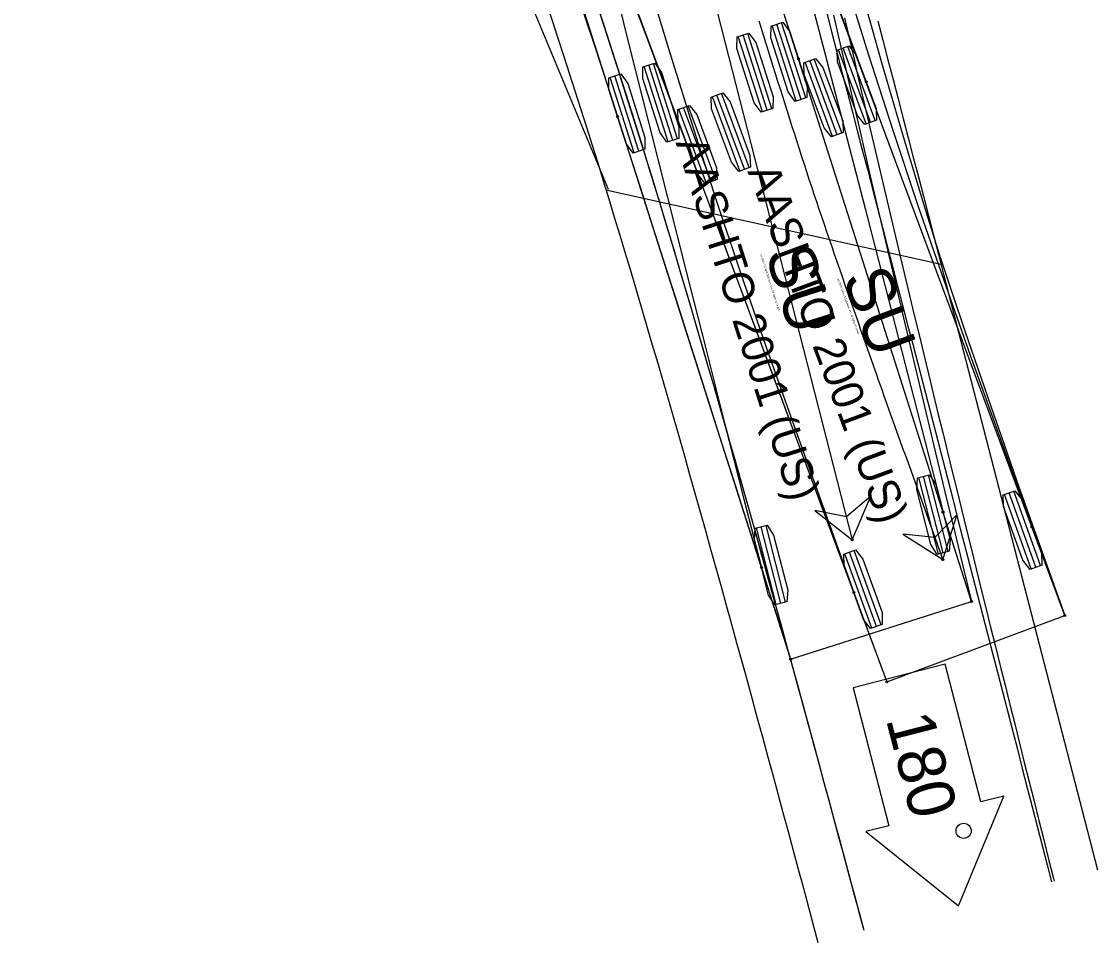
# Model space of a CAD drawing. Extents: x 916040 to 917457, y 328936 to 330267.
# Drawn here: x 916711.68 to 916757.01, y 329739.76 to 329778.57 of the extents above; entities that cross this region are included whole.
import ezdxf

# ---------------------------------------------------------------- set-up
doc = ezdxf.new("R2010")
doc.units = 0
for name, color, linetype in [('D_Roadway_Drive_Gravel', 7, 'Continuous'), ('SU_IntoDriveway', 7, 'Continuous'), ('SU_IntoDriveway_Lt', 7, 'Continuous'), ('SU_IntoDriveway_Rt', 7, 'Continuous')]:
    doc.layers.add(name, color=color, linetype=linetype)

msp = doc.modelspace()

# ---------------------------------------------------------------- linework, layer by layer
at = {"layer": 'D_Roadway_Drive_Gravel'}
msp.add_line((916736.405, 329771.493), (916728.256, 329791.111), dxfattribs=at)
at = {"layer": 'SU_IntoDriveway'}
for p, q in [((916736.303, 329771.473), (916750.419, 329768.338)), ((916750.587, 329751.49), (916746.714, 329750.489)), ((916752.089, 329745.681), (916750.587, 329751.49)), ((916746.714, 329750.489), (916748.216, 329744.68)), ((916751.154, 329741.308), (916753.057, 329745.931)), ((916753.057, 329745.931), (916752.089, 329745.681)), ((916748.216, 329744.68), (916747.248, 329744.43)), ((916747.248, 329744.43), (916751.154, 329741.308))]:
    msp.add_line(p, q, dxfattribs=at)
for points in [[(916733.813, 329779.293), (916734.054, 329778.564), (916734.295, 329777.832), (916734.534, 329777.095), (916734.773, 329776.356), (916735.01, 329775.612), (916735.247, 329774.866), (916735.483, 329774.117), (916735.719, 329773.365), (916735.953, 329772.61), (916736.187, 329771.853), (916736.42, 329771.093), (916736.652, 329770.331), (916736.883, 329769.567), (916737.113, 329768.801), (916737.343, 329768.033), (916737.572, 329767.264), (916737.8, 329766.492), (916738.028, 329765.719), (916738.255, 329764.944), (916738.481, 329764.168), (916738.707, 329763.39), (916738.932, 329762.611), (916739.156, 329761.831), (916739.38, 329761.049), (916739.604, 329760.266), (916739.826, 329759.482), (916740.048, 329758.698), (916740.27, 329757.912), (916740.491, 329757.125), (916740.712, 329756.337), (916740.932, 329755.549), (916741.152, 329754.759), (916741.371, 329753.969), (916741.59, 329753.178), (916741.808, 329752.387), (916742.026, 329751.595), (916742.244, 329750.802), (916742.461, 329750.008), (916742.678, 329749.214), (916742.895, 329748.419), (916743.111, 329747.624), (916743.327, 329746.828), (916743.543, 329746.032), (916743.758, 329745.236), (916743.973, 329744.438), (916744.188, 329743.641), (916744.402, 329742.843), (916744.617, 329742.045), (916744.831, 329741.246), (916745.045, 329740.447), (916745.228, 329739.759)], [(916735.954, 329779.19), (916736.196, 329778.453), (916736.437, 329777.712), (916736.677, 329776.967), (916736.916, 329776.22), (916737.154, 329775.469), (916737.391, 329774.716), (916737.628, 329773.96), (916737.864, 329773.202), (916738.098, 329772.441), (916738.332, 329771.678), (916738.565, 329770.913), (916738.798, 329770.145), (916739.029, 329769.376), (916739.26, 329768.605), (916739.49, 329767.832), (916739.719, 329767.058), (916739.947, 329766.282), (916740.175, 329765.505), (916740.402, 329764.726), (916740.628, 329763.946), (916740.854, 329763.165), (916741.079, 329762.382), (916741.303, 329761.599), (916741.527, 329760.814), (916741.75, 329760.028), (916741.973, 329759.241), (916742.195, 329758.454), (916742.417, 329757.665), (916742.638, 329756.876), (916742.859, 329756.086), (916743.079, 329755.295), (916743.298, 329754.503), (916743.518, 329753.711), (916743.736, 329752.918), (916743.955, 329752.125), (916744.173, 329751.33), (916744.39, 329750.536), (916744.608, 329749.741), (916744.825, 329748.945), (916745.041, 329748.148), (916745.257, 329747.352), (916745.473, 329746.555), (916745.689, 329745.757), (916745.904, 329744.959), (916746.119, 329744.161), (916746.334, 329743.362), (916746.548, 329742.563), (916746.763, 329741.763), (916746.977, 329740.964), (916747.161, 329740.275)], [(916735.954, 329779.19), (916736.196, 329778.453), (916736.437, 329777.712), (916736.677, 329776.967), (916736.916, 329776.22), (916737.154, 329775.469), (916737.391, 329774.716), (916737.628, 329773.96), (916737.864, 329773.202), (916738.098, 329772.441), (916738.332, 329771.678), (916738.565, 329770.913), (916738.798, 329770.145), (916739.029, 329769.376), (916739.26, 329768.605), (916739.49, 329767.832), (916739.719, 329767.058), (916739.947, 329766.282), (916740.175, 329765.505), (916740.402, 329764.726), (916740.628, 329763.946), (916740.854, 329763.165), (916741.079, 329762.382), (916741.303, 329761.599), (916741.527, 329760.814), (916741.75, 329760.028), (916741.973, 329759.241), (916742.195, 329758.454), (916742.417, 329757.665), (916742.638, 329756.876), (916742.859, 329756.086), (916743.079, 329755.295), (916743.298, 329754.503), (916743.518, 329753.711), (916743.736, 329752.918), (916743.955, 329752.125), (916744.173, 329751.33), (916744.39, 329750.536), (916744.608, 329749.741), (916744.825, 329748.945), (916745.041, 329748.148), (916745.257, 329747.352), (916745.473, 329746.555), (916745.689, 329745.757), (916745.904, 329744.959), (916746.119, 329744.161), (916746.334, 329743.362), (916746.548, 329742.563), (916746.763, 329741.763), (916746.977, 329740.964), (916747.161, 329740.275)], [(916735.99, 329779.08), (916736.246, 329778.3), (916736.499, 329777.518), (916736.751, 329776.736), (916737.001, 329775.952), (916737.249, 329775.167), (916737.496, 329774.382), (916737.742, 329773.595), (916737.985, 329772.808), (916738.228, 329772.019), (916738.469, 329771.23), (916738.708, 329770.44), (916738.947, 329769.649), (916739.184, 329768.858), (916739.42, 329768.066), (916739.655, 329767.273), (916739.889, 329766.48), (916740.122, 329765.686), (916740.354, 329764.891), (916740.585, 329764.096), (916740.815, 329763.301), (916741.044, 329762.505), (916741.272, 329761.708), (916741.499, 329760.911), (916741.726, 329760.114), (916741.952, 329759.316), (916742.177, 329758.518), (916742.402, 329757.719), (916742.626, 329756.92), (916742.849, 329756.121), (916743.071, 329755.322), (916743.293, 329754.522), (916743.515, 329753.721), (916743.736, 329752.921), (916743.956, 329752.12), (916744.176, 329751.319), (916744.395, 329750.518), (916744.614, 329749.716), (916744.833, 329748.915), (916745.051, 329748.113), (916745.269, 329747.311), (916745.486, 329746.508), (916745.703, 329745.706), (916745.919, 329744.903), (916746.135, 329744.1), (916746.351, 329743.297), (916746.567, 329742.494), (916746.782, 329741.691), (916746.997, 329740.887), (916747.161, 329740.275)], [(916745.6, 329778.923), (916745.815, 329778.098), (916746.03, 329777.274), (916746.245, 329776.45), (916746.46, 329775.627), (916746.674, 329774.805), (916746.888, 329773.983), (916747.101, 329773.162), (916747.314, 329772.341), (916747.527, 329771.521), (916747.74, 329770.701), (916747.952, 329769.882), (916748.165, 329769.064), (916748.377, 329768.246), (916748.588, 329767.428), (916748.8, 329766.611), (916749.011, 329765.794), (916749.223, 329764.978), (916749.434, 329764.161), (916749.645, 329763.346), (916749.856, 329762.53), (916750.066, 329761.715), (916750.277, 329760.901), (916750.487, 329760.086), (916750.698, 329759.272), (916750.908, 329758.458), (916751.118, 329757.645), (916751.328, 329756.832), (916751.538, 329756.019), (916751.748, 329755.206), (916751.957, 329754.393), (916752.167, 329753.581), (916752.377, 329752.769), (916752.586, 329751.957), (916752.796, 329751.145), (916753.005, 329750.334), (916753.214, 329749.523), (916753.424, 329748.711), (916753.633, 329747.9), (916753.842, 329747.09), (916754.051, 329746.279), (916754.26, 329745.469), (916754.469, 329744.658), (916754.678, 329743.848), (916754.887, 329743.038), (916755.072, 329742.321)], [(916745.6, 329778.923), (916745.815, 329778.098), (916746.03, 329777.274), (916746.245, 329776.45), (916746.46, 329775.627), (916746.674, 329774.805), (916746.888, 329773.983), (916747.101, 329773.162), (916747.314, 329772.341), (916747.527, 329771.521), (916747.74, 329770.701), (916747.952, 329769.882), (916748.165, 329769.064), (916748.377, 329768.246), (916748.588, 329767.428), (916748.8, 329766.611), (916749.011, 329765.794), (916749.223, 329764.978), (916749.434, 329764.161), (916749.645, 329763.346), (916749.856, 329762.53), (916750.066, 329761.715), (916750.277, 329760.901), (916750.487, 329760.086), (916750.698, 329759.272), (916750.908, 329758.458), (916751.118, 329757.645), (916751.328, 329756.832), (916751.538, 329756.019), (916751.748, 329755.206), (916751.957, 329754.393), (916752.167, 329753.581), (916752.377, 329752.769), (916752.586, 329751.957), (916752.796, 329751.145), (916753.005, 329750.334), (916753.214, 329749.523), (916753.424, 329748.711), (916753.633, 329747.9), (916753.842, 329747.09), (916754.051, 329746.279), (916754.26, 329745.469), (916754.469, 329744.658), (916754.678, 329743.848), (916754.887, 329743.038), (916755.072, 329742.321)], [(916746.351, 329778.729), (916746.544, 329777.884), (916746.738, 329777.041), (916746.933, 329776.199), (916747.127, 329775.358), (916747.323, 329774.519), (916747.518, 329773.682), (916747.714, 329772.846), (916747.91, 329772.011), (916748.106, 329771.177), (916748.303, 329770.344), (916748.5, 329769.513), (916748.697, 329768.682), (916748.895, 329767.853), (916749.093, 329767.024), (916749.292, 329766.196), (916749.49, 329765.37), (916749.689, 329764.544), (916749.889, 329763.718), (916750.088, 329762.894), (916750.288, 329762.07), (916750.488, 329761.248), (916750.689, 329760.425), (916750.89, 329759.604), (916751.091, 329758.783), (916751.292, 329757.962), (916751.493, 329757.142), (916751.695, 329756.323), (916751.897, 329755.504), (916752.099, 329754.686), (916752.301, 329753.868), (916752.504, 329753.051), (916752.707, 329752.234), (916752.91, 329751.417), (916753.113, 329750.601), (916753.316, 329749.786), (916753.52, 329748.97), (916753.723, 329748.155), (916753.927, 329747.34), (916754.131, 329746.526), (916754.336, 329745.712), (916754.54, 329744.898), (916754.744, 329744.085), (916754.949, 329743.272), (916755.154, 329742.459), (916755.181, 329742.349)], [(916747.75, 329778.603), (916747.966, 329777.779), (916748.18, 329776.954), (916748.395, 329776.131), (916748.609, 329775.308), (916748.823, 329774.486), (916749.037, 329773.665), (916749.25, 329772.844), (916749.463, 329772.024), (916749.676, 329771.204), (916749.888, 329770.384), (916750.101, 329769.566), (916750.313, 329768.747), (916750.524, 329767.929), (916750.736, 329767.112), (916750.948, 329766.295), (916751.159, 329765.478), (916751.37, 329764.662), (916751.581, 329763.846), (916751.792, 329763.031), (916752.003, 329762.216), (916752.213, 329761.401), (916757.009, 329742.821)]]:
    msp.add_lwpolyline(points, dxfattribs=at)
msp.add_circle((916751.371, 329744.463), 0.32, dxfattribs=at)
at = {"layer": 'SU_IntoDriveway_Lt'}
for p, q in [((916736.164, 329797.863), (916746.678, 329756.728)), ((916751.704, 329754.133), (916742.585, 329782.714)), ((916734.964, 329780.282), (916744.083, 329751.702)), ((916744.717, 329775.347), (916743.704, 329778.522)), ((916743.288, 329774.891), (916742.275, 329778.066)), ((916744.32, 329775.22), (916743.307, 329778.396)), ((916744.519, 329775.283), (916743.505, 329778.459)), ((916742.891, 329774.764), (916741.878, 329777.94)), ((916743.09, 329774.827), (916742.076, 329778.003)), ((916739.12, 329773.561), (916738.107, 329776.737)), ((916739.318, 329773.624), (916738.305, 329776.8)), ((916737.691, 329773.105), (916736.678, 329776.281)), ((916737.889, 329773.168), (916736.876, 329776.344)), ((916738.922, 329773.498), (916737.908, 329776.673)), ((916737.493, 329773.042), (916736.479, 329776.217)), ((916750.713, 329756.231), (916749.886, 329759.461)), ((916750.31, 329756.128), (916749.483, 329759.357)), ((916750.512, 329756.18), (916749.684, 329759.409)), ((916743.467, 329753.996), (916742.643, 329757.226)), ((916743.669, 329754.048), (916742.845, 329757.278)), ((916743.871, 329754.099), (916743.047, 329757.329)), ((916744.083, 329751.702), (916751.704, 329754.133)), ((916751.704, 329754.133), (916751.704, 329754.133))]:
    msp.add_line(p, q, dxfattribs=at)
for points in [[(916734.83, 329780.501), (916735.875, 329777.387), (916736.787, 329774.566)], [(916736.501, 329780.691), (916737.284, 329777.544), (916738.076, 329774.384), (916738.875, 329771.214), (916739.68, 329768.034), (916740.489, 329764.845), (916741.302, 329761.649), (916742.117, 329758.447), (916742.853, 329755.56)], [(916744.645, 329780.618), (916745.509, 329777.298), (916746.366, 329773.988), (916747.217, 329770.69), (916748.064, 329767.4), (916748.907, 329764.117), (916749.747, 329760.841), (916750.502, 329757.898)], [(916743.473, 329779.891), (916744.409, 329776.998)], [(916735.34, 329778.996), (916735.827, 329777.533), (916736.31, 329776.054), (916736.789, 329774.561), (916737.269, 329773.058), (916737.751, 329771.545), (916738.237, 329770.024), (916738.724, 329768.496), (916739.214, 329766.962), (916739.705, 329765.422), (916740.198, 329763.877), (916740.692, 329762.327), (916741.188, 329760.774), (916741.685, 329759.217), (916742.183, 329757.656), (916742.682, 329756.093), (916743.181, 329754.527), (916743.682, 329752.958), (916744.083, 329751.702)], [(916745.892, 329778.832), (916746.276, 329777.129), (916746.661, 329775.432), (916747.048, 329773.742), (916747.435, 329772.058), (916747.824, 329770.379), (916748.215, 329768.705), (916748.606, 329767.036), (916749, 329765.371), (916749.394, 329763.71), (916749.789, 329762.052), (916750.186, 329760.397), (916750.584, 329758.745), (916750.983, 329757.096), (916751.383, 329755.449), (916751.704, 329754.133)]]:
    msp.add_lwpolyline(points, dxfattribs=at)
for points in [[(916744.766, 329775.362), (916744.271, 329775.204), (916743.98, 329775.601), (916743.25, 329777.888), (916743.258, 329778.38), (916743.753, 329778.538), (916744.044, 329778.141), (916744.774, 329775.855)], [(916743.337, 329774.906), (916742.842, 329774.748), (916742.551, 329775.145), (916741.821, 329777.432), (916741.829, 329777.924), (916742.324, 329778.082), (916742.615, 329777.685), (916743.345, 329775.399)], [(916739.368, 329773.64), (916738.872, 329773.482), (916738.581, 329773.879), (916737.852, 329776.165), (916737.859, 329776.657), (916738.354, 329776.816), (916738.646, 329776.419), (916739.375, 329774.132)], [(916737.939, 329773.184), (916737.443, 329773.026), (916737.152, 329773.423), (916736.423, 329775.709), (916736.43, 329776.202), (916736.925, 329776.36), (916737.217, 329775.963), (916737.946, 329773.676)], [(916750.763, 329756.244), (916750.26, 329756.115), (916749.992, 329756.528), (916749.397, 329758.853), (916749.433, 329759.344), (916749.936, 329759.473), (916750.204, 329759.06), (916750.799, 329756.735)], [(916746.678, 329756.728), (916747.464, 329758.567), (916746.43, 329757.697), (916745.105, 329757.964)], [(916743.921, 329754.112), (916743.417, 329753.984), (916743.15, 329754.397), (916742.557, 329756.723), (916742.593, 329757.214), (916743.097, 329757.342), (916743.364, 329756.929), (916743.957, 329754.603)]]:
    msp.add_lwpolyline(points, close=True, dxfattribs=at)
for centre in [(916744.409, 329776.998), (916736.787, 329774.566), (916750.502, 329757.898), (916746.678, 329756.728), (916742.853, 329755.56), (916751.704, 329754.133), (916744.083, 329751.702)]:
    msp.add_circle(centre, 0.0417, dxfattribs=at)
at = {"layer": 'SU_IntoDriveway_Rt'}
for p, q in [((916755.636, 329753.539), (916745.168, 329781.653)), ((916737.671, 329778.862), (916748.138, 329750.748)), ((916747.258, 329774.251), (916746.095, 329777.374)), ((916747.453, 329774.323), (916746.29, 329777.447)), ((916747.648, 329774.396), (916746.485, 329777.52)), ((916745.852, 329773.727), (916744.689, 329776.851)), ((916746.047, 329773.8), (916744.884, 329776.924)), ((916746.242, 329773.873), (916745.079, 329776.996)), ((916741.947, 329772.273), (916740.784, 329775.397)), ((916742.142, 329772.346), (916740.979, 329775.47)), ((916742.338, 329772.419), (916741.175, 329775.543)), ((916740.541, 329771.75), (916739.378, 329774.874)), ((916740.737, 329771.823), (916739.574, 329774.947)), ((916740.932, 329771.895), (916739.769, 329775.019)), ((916754.22, 329755.5), (916753.09, 329758.635)), ((916754.416, 329755.57), (916753.286, 329758.706)), ((916754.612, 329755.641), (916753.481, 329758.776)), ((916747.501, 329753.007), (916746.37, 329756.143)), ((916747.697, 329753.078), (916746.566, 329756.213)), ((916747.893, 329753.148), (916746.762, 329756.284)), ((916748.138, 329750.748), (916755.636, 329753.539)), ((916755.636, 329753.539), (916755.636, 329753.539))]:
    msp.add_line(p, q, dxfattribs=at)
for points in [[(916714.9, 329827.336), (916716.624, 329826.516), (916719.394, 329824.952), (916722.017, 329823.153), (916724.473, 329821.132), (916726.744, 329818.905), (916728.813, 329816.489), (916730.676, 329813.886), (916732.407, 329811.043), (916734.015, 329808.062), (916735.521, 329805.02), (916736.959, 329801.953), (916738.338, 329798.858), (916739.658, 329795.744), (916740.929, 329792.618), (916742.163, 329789.488), (916743.371, 329786.359), (916744.562, 329783.229), (916745.741, 329780.1), (916746.912, 329776.97), (916747.262, 329776.031)], [(916711.681, 329820.012), (916713.026, 329819.37), (916715.187, 329818.147), (916717.234, 329816.74), (916719.15, 329815.161), (916720.921, 329813.42), (916722.534, 329811.532), (916724, 329809.477), (916725.465, 329807.067), (916726.905, 329804.395), (916728.313, 329801.548), (916729.688, 329798.618), (916731.002, 329795.668), (916732.27, 329792.675), (916733.502, 329789.644), (916734.71, 329786.581), (916735.901, 329783.495), (916737.081, 329780.396), (916738.252, 329777.288), (916739.416, 329774.174), (916739.765, 329773.239)], [(916733.541, 329819.025), (916734.805, 329817.241), (916736.698, 329814.129), (916738.312, 329810.863), (916739.636, 329807.47), (916740.66, 329803.974), (916741.375, 329800.403), (916741.828, 329796.849), (916742.441, 329793.437), (916743.249, 329790.111), (916744.236, 329786.915), (916745.332, 329783.685), (916746.347, 329780.42), (916747.355, 329777.205), (916748.381, 329773.997), (916749.443, 329770.819), (916750.538, 329767.665), (916751.649, 329764.509), (916752.776, 329761.365), (916753.904, 329758.22), (916754.243, 329757.279)], [(916729.617, 329812.289), (916730.534, 329810.719), (916731.875, 329808.004), (916732.974, 329805.182), (916733.824, 329802.275), (916734.417, 329799.306), (916734.749, 329796.295), (916734.886, 329793.193), (916735.306, 329789.992), (916736.003, 329786.809), (916736.956, 329783.619), (916737.99, 329780.532), (916738.939, 329777.427), (916739.916, 329774.276), (916740.916, 329771.131), (916741.964, 329767.984), (916743.053, 329764.84), (916744.156, 329761.707), (916745.278, 329758.575), (916746.401, 329755.445), (916746.74, 329754.504)], [(916746.965, 329780.139), (916747.445, 329778.496), (916747.907, 329776.848), (916748.383, 329775.211), (916748.864, 329773.58), (916749.35, 329771.954), (916749.849, 329770.337), (916750.357, 329768.727), (916750.884, 329767.128), (916751.421, 329765.537), (916751.962, 329763.949), (916752.51, 329762.365), (916753.06, 329760.783), (916753.617, 329759.206), (916754.178, 329757.631), (916754.736, 329756.056), (916755.298, 329754.482), (916755.636, 329753.539)], [(916737.468, 329779.372), (916738.038, 329777.858), (916738.606, 329776.343), (916739.172, 329774.83), (916739.736, 329773.317), (916740.302, 329771.796), (916740.87, 329770.27), (916741.44, 329768.74), (916742.011, 329767.204), (916742.585, 329765.664), (916743.16, 329764.118), (916743.737, 329762.569), (916744.315, 329761.018), (916744.893, 329759.465), (916745.471, 329757.911), (916746.051, 329756.355), (916746.63, 329754.798), (916747.21, 329753.241), (916747.79, 329751.683), (916748.138, 329750.748)], [(916742.739, 329778.602), (916742.837, 329778.283), (916742.937, 329777.966), (916743.037, 329777.647), (916743.138, 329777.33), (916743.238, 329777.012), (916743.338, 329776.694), (916743.437, 329776.376), (916743.535, 329776.057), (916743.636, 329775.739), (916743.734, 329775.421), (916743.835, 329775.103), (916743.935, 329774.785), (916744.036, 329774.467), (916744.137, 329774.15), (916744.239, 329773.832), (916744.341, 329773.515), (916744.444, 329773.198), (916744.546, 329772.881), (916744.649, 329772.564), (916744.751, 329772.246), (916744.855, 329771.93), (916744.958, 329771.613), (916745.063, 329771.296), (916745.168, 329770.98), (916745.275, 329770.664), (916745.383, 329770.349), (916745.489, 329770.033), (916745.597, 329769.717), (916745.703, 329769.402), (916745.811, 329769.086), (916745.919, 329768.771), (916746.028, 329768.456), (916746.138, 329768.141), (916746.248, 329767.826), (916746.356, 329767.511), (916746.465, 329767.196), (916746.573, 329766.881), (916746.684, 329766.566), (916746.795, 329766.252), (916746.907, 329765.938), (916747.017, 329765.623), (916747.127, 329765.309), (916747.238, 329764.995), (916747.348, 329764.68), (916747.459, 329764.365), (916747.567, 329764.05), (916747.68, 329763.736), (916747.79, 329763.422), (916747.903, 329763.108), (916748.014, 329762.794), (916748.127, 329762.48), (916748.239, 329762.166), (916748.35, 329761.852), (916748.463, 329761.539), (916748.575, 329761.224), (916748.688, 329760.911), (916748.8, 329760.597), (916748.914, 329760.284), (916749.027, 329759.97), (916749.139, 329759.656), (916749.253, 329759.343), (916749.365, 329759.029), (916749.477, 329758.715), (916749.588, 329758.401), (916749.701, 329758.087), (916749.813, 329757.773), (916749.927, 329757.46), (916750.04, 329757.146), (916750.153, 329756.833), (916750.264, 329756.519), (916750.378, 329756.205), (916750.491, 329755.892)]]:
    msp.add_lwpolyline(points, dxfattribs=at)
for points in [[(916747.697, 329774.414), (916747.209, 329774.233), (916746.9, 329774.615), (916746.062, 329776.864), (916746.046, 329777.356), (916746.534, 329777.538), (916746.843, 329777.155), (916747.681, 329774.906)], [(916746.291, 329773.891), (916745.803, 329773.709), (916745.494, 329774.092), (916744.656, 329776.341), (916744.64, 329776.833), (916745.128, 329777.014), (916745.437, 329776.632), (916746.275, 329774.383)], [(916742.386, 329772.437), (916741.899, 329772.255), (916741.589, 329772.638), (916740.752, 329774.887), (916740.736, 329775.379), (916741.223, 329775.561), (916741.533, 329775.178), (916742.37, 329772.929)], [(916740.98, 329771.913), (916740.493, 329771.732), (916740.183, 329772.115), (916739.346, 329774.364), (916739.33, 329774.856), (916739.817, 329775.037), (916740.127, 329774.655), (916740.964, 329772.405)], [(916754.661, 329755.658), (916754.172, 329755.482), (916753.866, 329755.868), (916753.052, 329758.125), (916753.041, 329758.618), (916753.53, 329758.794), (916753.836, 329758.408), (916754.65, 329756.151)], [(916750.491, 329755.892), (916751.098, 329757.797), (916750.152, 329756.832), (916748.808, 329756.971)], [(916747.942, 329753.166), (916747.453, 329752.99), (916747.147, 329753.375), (916746.333, 329755.633), (916746.322, 329756.125), (916746.811, 329756.302), (916747.117, 329755.916), (916747.931, 329753.658)]]:
    msp.add_lwpolyline(points, close=True, dxfattribs=at)
for centre in [(916747.262, 329776.031), (916739.765, 329773.239), (916754.243, 329757.279), (916750.491, 329755.892), (916746.74, 329754.504), (916755.636, 329753.539), (916748.138, 329750.748)]:
    msp.add_circle(centre, 0.0417, dxfattribs=at)

# ---------------------------------------------------------------- texts
at = {"layer": 'SU_IntoDriveway'}
msp.add_text('180', height=2, rotation=284.4957, dxfattribs=at).set_placement((916748.088, 329749.172))
at = {"layer": 'SU_IntoDriveway_Lt'}
for s, height, p in [('AASHTO 2001 (US)', 1.33333, (916739.229, 329773.471)), ('SU', 2, (916742.994, 329768.799)), ('(c) 2016 Transoft Solutions, Inc. All rights reserved.', 0.08, (916742.8, 329768.749))]:
    msp.add_text(s, height=height, rotation=287.6961, dxfattribs=at).set_placement(p)
at = {"layer": 'SU_IntoDriveway_Rt'}
for s, height, p in [('AASHTO 2001 (US)', 1.33333, (916742.256, 329772.261)), ('SU', 2, (916746.238, 329767.774)), ('(c) 2016 Transoft Solutions, Inc. All rights reserved.', 0.08, (916746.047, 329767.715))]:
    msp.add_text(s, height=height, rotation=290.4205, dxfattribs=at).set_placement(p)

doc.saveas('drawing.dxf')
